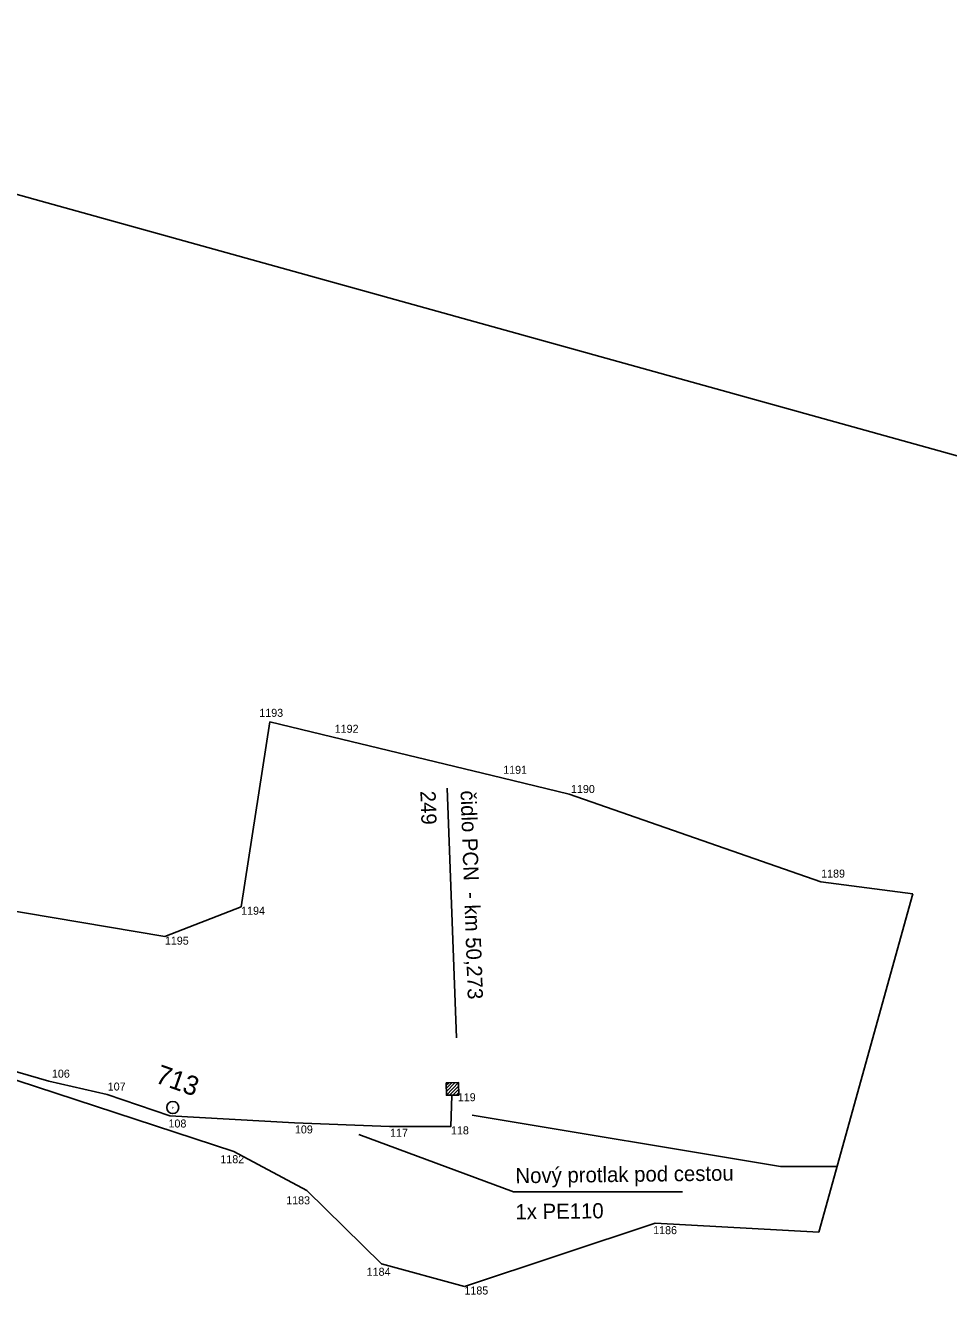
# Model space of a CAD drawing. Extents: x -678084 to -677195, y -1006706 to -1006195.
# Drawn here: x -677523.2 to -677407.9, y -1006465.7 to -1006307.1 of the extents above; entities that cross this region are included whole.
import ezdxf

# ---------------------------------------------------------------- set-up
doc = ezdxf.new("R2010")
doc.units = 0
for name, color, linetype in [('rozpiska - rámy', 7, 'Continuous'), ('SSZT nové - lomové body', 7, 'Continuous'), ('SSZT_nové', 7, 'Continuous'), ('Stávající ŽBP', 7, 'Continuous'), ('SŽDC', 7, 'Continuous'), ('SŽDC - body', 7, 'Continuous')]:
    doc.layers.add(name, color=color, linetype=linetype)

msp = doc.modelspace()

# ---------------------------------------------------------------- linework, layer by layer
at = {"layer": 'rozpiska - rámy'}
msp.add_line((-677600.1, -1006307.13), (-677397.78, -1006363.43), dxfattribs=at)
at = {"layer": 'SSZT nové - lomové body'}
for p, q in [((-677520.22, -1006439.09), (-677520.22, -1006439.09)), ((-677512.96, -1006440.72), (-677512.96, -1006440.72)), ((-677469.9, -1006440.86), (-677469.9, -1006440.86)), ((-677505.14, -1006443.41), (-677505.14, -1006443.41)), ((-677489.54, -1006444.26), (-677489.54, -1006444.26)), ((-677477.69, -1006444.72), (-677477.69, -1006444.72)), ((-677470.01, -1006444.72), (-677470.01, -1006444.72))]:
    msp.add_line(p, q, dxfattribs=at)
at = {"layer": 'SSZT_nové'}
for p, q in [((-677470.48, -1006402.46), (-677469.33, -1006433.67)), ((-677470.61, -1006440), (-677469.89, -1006439.26)), ((-677470.61, -1006439.59), (-677470.3, -1006439.27)), ((-677470.6, -1006440.42), (-677469.47, -1006439.25)), ((-677470.59, -1006440.83), (-677469.06, -1006439.25)), ((-677470.18, -1006440.82), (-677469.05, -1006439.66)), ((-677469.77, -1006440.81), (-677469.05, -1006440.07)), ((-677469.35, -1006440.81), (-677469.04, -1006440.48)), ((-677467.36, -1006443.32), (-677428.84, -1006449.73)), ((-677481.51, -1006445.75), (-677462.2, -1006452.88)), ((-677421.8, -1006449.73), (-677428.84, -1006449.73)), ((-677441.09, -1006452.88), (-677462.2, -1006452.88))]:
    msp.add_line(p, q, dxfattribs=at)
for points in [[(-677540.71, -1006433.07), (-677534.99, -1006434.85), (-677528.03, -1006436.83), (-677520.22, -1006439.09), (-677512.96, -1006440.72), (-677505.14, -1006443.41), (-677489.54, -1006444.26)], [(-677489.54, -1006444.26), (-677477.69, -1006444.72), (-677470.01, -1006444.72), (-677469.9, -1006440.86)]]:
    msp.add_lwpolyline(points, dxfattribs=at)
msp.add_lwpolyline([(-677470.62, -1006439.27), (-677469.06, -1006439.25), (-677469.03, -1006440.8), (-677470.59, -1006440.83)], close=True, dxfattribs=at)
at = {"layer": 'Stávající ŽBP'}
msp.add_line((-677504.81, -1006442.36), (-677504.72, -1006442.39), dxfattribs=at)
msp.add_circle((-677504.76, -1006442.37), 0.756, dxfattribs=at)
at = {"layer": 'SŽDC'}
for p, q in [((-677492.65, -1006394.17), (-677496.22, -1006417.27)), ((-677484.89, -1006396.04), (-677492.65, -1006394.17)), ((-677463.66, -1006401.16), (-677484.89, -1006396.04)), ((-677455.24, -1006403.19), (-677463.66, -1006401.16)), ((-677423.8, -1006414.14), (-677455.24, -1006403.19)), ((-677505.74, -1006421.01), (-677548.06, -1006413.85)), ((-677412.32, -1006415.66), (-677423.8, -1006414.14)), ((-677424.09, -1006457.96), (-677412.32, -1006415.66)), ((-677496.22, -1006417.27), (-677505.74, -1006421.01)), ((-677532.59, -1006436.26), (-677497.11, -1006447.85)), ((-677497.11, -1006447.85), (-677488.02, -1006452.74)), ((-677488.02, -1006452.74), (-677478.69, -1006461.9)), ((-677468.33, -1006464.73), (-677444.49, -1006456.8)), ((-677444.49, -1006456.8), (-677424.09, -1006457.96)), ((-677478.69, -1006461.9), (-677468.33, -1006464.73))]:
    msp.add_line(p, q, dxfattribs=at)
at = {"layer": 'SŽDC - body'}
for p, q in [((-677492.65, -1006394.17), (-677492.65, -1006394.17)), ((-677484.89, -1006396.04), (-677484.89, -1006396.04)), ((-677463.66, -1006401.16), (-677463.66, -1006401.16)), ((-677455.24, -1006403.19), (-677455.24, -1006403.19)), ((-677423.8, -1006414.14), (-677423.8, -1006414.14)), ((-677412.32, -1006415.66), (-677412.32, -1006415.66)), ((-677496.22, -1006417.27), (-677496.22, -1006417.27)), ((-677505.74, -1006421.01), (-677505.74, -1006421.01)), ((-677497.11, -1006447.85), (-677497.11, -1006447.85)), ((-677488.02, -1006452.74), (-677488.02, -1006452.74)), ((-677444.49, -1006456.8), (-677444.49, -1006456.8)), ((-677424.09, -1006457.96), (-677424.09, -1006457.96)), ((-677478.69, -1006461.9), (-677478.69, -1006461.9)), ((-677468.33, -1006464.73), (-677468.33, -1006464.73))]:
    msp.add_line(p, q, dxfattribs=at)

# ---------------------------------------------------------------- texts
at = {"layer": 'SSZT nové - lomové body'}
for s, p in [('106', (-677519.85, -1006438.63)), ('107', (-677512.88, -1006440.24)), ('119', (-677469.16, -1006441.58)), ('108', (-677505.29, -1006444.86)), ('109', (-677489.5, -1006445.6)), ('117', (-677477.62, -1006446.02)), ('118', (-677470.01, -1006445.72))]:
    msp.add_text(s, height=1, dxfattribs=at).set_placement(p)
at = {"layer": 'SSZT_nové'}
for s, rotation, p in [('249', 272.0108, (-677473.84, -1006402.82)), ('čidlo PCN  - km 50,273', 272.0108, (-677468.82, -1006402.77)), ('Nový protlak pod cestou', 0.7098, (-677461.95, -1006451.83)), ('1x PE110', 0.7098, (-677461.95, -1006456.34))]:
    msp.add_text(s, height=1.9, rotation=rotation, dxfattribs=at).set_placement(p)
at = {"layer": 'Stávající ŽBP'}
msp.add_text('713', height=2.4, rotation=340.5082, dxfattribs=at).set_placement((-677507.07, -1006439.21))
at = {"layer": 'SŽDC - body'}
for s, p in [('1193', (-677493.95, -1006393.54)), ('1192', (-677484.53, -1006395.53)), ('1191', (-677463.49, -1006400.66)), ('1190', (-677455.02, -1006403.06)), ('1189', (-677423.78, -1006413.63)), ('1194', (-677496.22, -1006418.27)), ('1195', (-677505.74, -1006422.01)), ('1182', (-677498.81, -1006449.32)), ('1183', (-677490.59, -1006454.46)), ('1186', (-677444.76, -1006458.19)), ('1184', (-677480.54, -1006463.39)), ('1185', (-677468.33, -1006465.73))]:
    msp.add_text(s, height=1, dxfattribs=at).set_placement(p)

doc.saveas('drawing.dxf')
